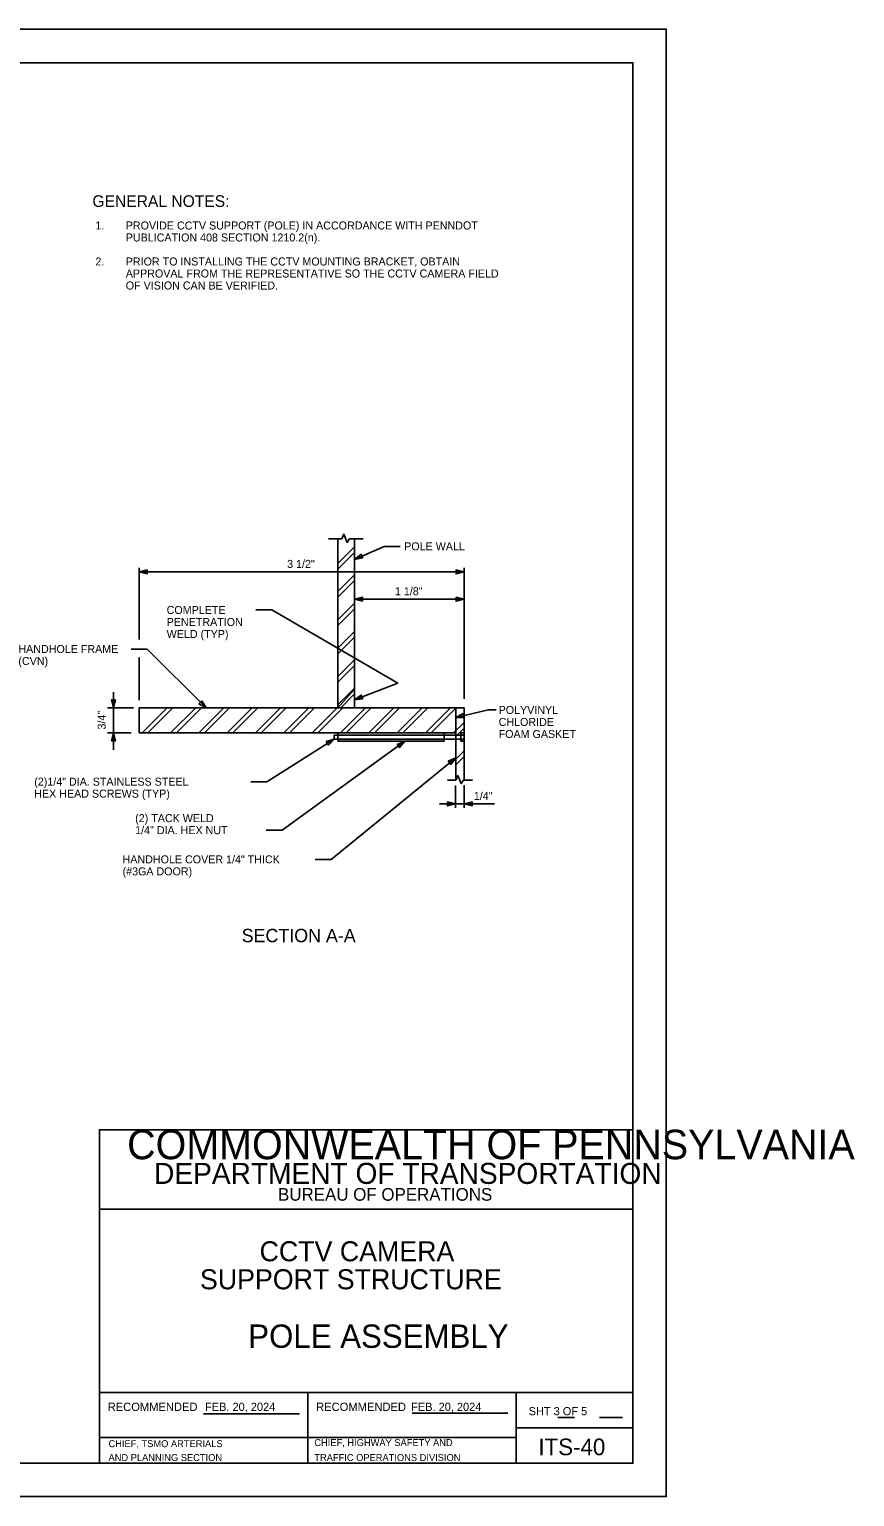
# Model space of a CAD drawing. Extents: x 1299104.7 to 1299141.5, y 239689.9 to 239711.9.
# Drawn here: x 1299129.17 to 1299141.55, y 239689.89 to 239711.89 of the extents above; entities that cross this region are included whole.
import ezdxf

# ---------------------------------------------------------------- set-up
doc = ezdxf.new("R2010")
doc.units = 0
for name, color, linetype in [('1', 7, 'Continuous'), ('2', 7, 'Continuous'), ('DIM TXT', 7, 'Continuous'), ('GS_plotshape_p', 7, 'Continuous'), ('Level 1', 7, 'Continuous'), ('Level 3', 7, 'Continuous'), ('Level 8', 7, 'Continuous'), ('PTEXT', 7, 'Continuous')]:
    doc.layers.add(name, color=color, linetype=linetype)

msp = doc.modelspace()

# ---------------------------------------------------------------- linework, layer by layer
at = {"layer": '1'}
for p, q in [((1299131.785, 239691.129), (1299133.222, 239691.129)), ((1299134.91, 239691.138), (1299136.347, 239691.138)), ((1299130.222, 239690.774), (1299133.347, 239690.774))]:
    msp.add_line(p, q, dxfattribs=at)
at = {"layer": 'DIM TXT'}
for p, q in [((1299138.722, 239711.886), (1299138.722, 239711.886)), ((1299133.742, 239701.302), (1299135.69, 239701.302)), ((1299133.742, 239701.245), (1299135.69, 239701.245)), ((1299135.565, 239701.302), (1299135.565, 239701.245)), ((1299135.643, 239701.211), (1299135.643, 239701.336)), ((1299135.643, 239701.336), (1299135.69, 239701.336)), ((1299135.643, 239701.211), (1299135.69, 239701.211)), ((1299138.722, 239689.886), (1299138.722, 239689.886))]:
    msp.add_line(p, q, dxfattribs=at)
at = {"layer": 'GS_plotshape_p'}
msp.add_lwpolyline([(1299104.722, 239711.886), (1299138.722, 239711.886), (1299138.722, 239689.886), (1299104.722, 239689.886)], close=True, dxfattribs=at)
at = {"layer": 'Level 1'}
for p, q in [((1299130.222, 239691.448), (1299138.222, 239691.448)), ((1299133.347, 239690.386), (1299133.347, 239691.448)), ((1299136.472, 239690.386), (1299136.472, 239691.448)), ((1299136.472, 239690.917), (1299138.222, 239690.917)), ((1299137.097, 239691.073), (1299137.347, 239691.073)), ((1299137.722, 239691.073), (1299138.066, 239691.073)), ((1299133.347, 239690.774), (1299136.472, 239690.774))]:
    msp.add_line(p, q, dxfattribs=at)
for points in [[(1299138.222, 239690.386), (1299106.222, 239690.386), (1299106.222, 239711.386), (1299138.222, 239711.386)], [(1299130.222, 239690.386), (1299138.222, 239690.386), (1299138.222, 239695.386), (1299130.222, 239695.386)], [(1299130.222, 239695.386), (1299138.222, 239695.386), (1299138.222, 239694.198), (1299130.222, 239694.198)]]:
    msp.add_lwpolyline(points, close=True, dxfattribs=at)
at = {"layer": 'Level 3'}
for p, q in [((1299133.798, 239704.246), (1299133.798, 239701.711)), ((1299134.048, 239704.246), (1299134.048, 239701.711)), ((1299135.69, 239701.711), (1299130.817, 239701.711)), ((1299130.817, 239701.336), (1299130.817, 239701.711)), ((1299135.565, 239701.336), (1299135.565, 239701.711)), ((1299135.69, 239700.628), (1299135.69, 239701.711)), ((1299130.817, 239701.336), (1299135.565, 239701.336)), ((1299133.742, 239701.302), (1299133.742, 239701.245)), ((1299133.797, 239701.336), (1299133.797, 239701.211)), ((1299134.256, 239701.336), (1299133.798, 239701.336)), ((1299135.391, 239701.336), (1299135.391, 239701.211)), ((1299135.565, 239700.628), (1299135.565, 239701.336)), ((1299133.797, 239701.211), (1299135.391, 239701.211))]:
    msp.add_line(p, q, dxfattribs=at)
for points in [[(1299134.048, 239701.994), (1299133.798, 239701.711), (1299134.048, 239701.711)], [(1299133.742, 239701.302), (1299133.742, 239701.245), (1299135.643, 239701.245), (1299135.643, 239701.211), (1299135.69, 239701.211), (1299135.69, 239701.336), (1299135.643, 239701.336), (1299135.643, 239701.302)]]:
    msp.add_lwpolyline(points, close=True, dxfattribs=at)
at = {"layer": 'Level 8'}
for p, q in [((1299133.659, 239704.246), (1299133.856, 239704.246)), ((1299133.798, 239703.879), (1299134.048, 239704.129)), ((1299133.974, 239704.246), (1299134.179, 239704.246)), ((1299134.048, 239703.939), (1299134.492, 239704.134)), ((1299134.732, 239704.134), (1299134.492, 239704.134)), ((1299133.798, 239703.794), (1299134.048, 239704.044)), ((1299133.798, 239703.879), (1299133.798, 239703.879)), ((1299130.817, 239702.735), (1299130.817, 239703.811)), ((1299130.817, 239703.751), (1299135.69, 239703.751)), ((1299133.798, 239703.455), (1299134.048, 239703.705)), ((1299135.69, 239701.847), (1299135.69, 239703.811)), ((1299133.798, 239703.37), (1299134.048, 239703.62)), ((1299135.69, 239703.56), (1299135.69, 239703.281)), ((1299133.798, 239703.03), (1299134.048, 239703.28)), ((1299134.048, 239703.066), (1299134.048, 239703.401)), ((1299134.048, 239703.341), (1299135.69, 239703.341)), ((1299132.566, 239703.18), (1299132.806, 239703.18)), ((1299133.798, 239702.946), (1299134.048, 239703.196)), ((1299133.798, 239702.606), (1299134.048, 239702.856)), ((1299133.798, 239702.521), (1299134.048, 239702.771)), ((1299130.701, 239702.595), (1299130.941, 239702.595)), ((1299131.821, 239701.711), (1299130.941, 239702.595)), ((1299130.817, 239701.83), (1299130.817, 239702.466)), ((1299133.798, 239702.182), (1299134.048, 239702.432)), ((1299133.798, 239702.097), (1299134.048, 239702.347)), ((1299130.432, 239701.949), (1299130.432, 239701.083)), ((1299133.798, 239701.758), (1299134.048, 239702.008)), ((1299133.84, 239701.715), (1299134.048, 239701.923)), ((1299130.734, 239701.712), (1299130.342, 239701.712)), ((1299130.866, 239701.336), (1299131.241, 239701.711)), ((1299130.951, 239701.336), (1299131.326, 239701.711)), ((1299131.291, 239701.336), (1299131.666, 239701.711)), ((1299131.376, 239701.336), (1299131.751, 239701.711)), ((1299131.715, 239701.336), (1299132.09, 239701.711)), ((1299131.8, 239701.336), (1299132.175, 239701.711)), ((1299132.139, 239701.336), (1299132.514, 239701.711)), ((1299132.224, 239701.336), (1299132.599, 239701.711)), ((1299132.563, 239701.336), (1299132.938, 239701.711)), ((1299132.648, 239701.336), (1299133.023, 239701.711)), ((1299132.988, 239701.336), (1299133.363, 239701.711)), ((1299133.073, 239701.336), (1299133.448, 239701.711)), ((1299133.412, 239701.336), (1299133.787, 239701.711)), ((1299133.497, 239701.336), (1299133.872, 239701.711)), ((1299133.836, 239701.336), (1299134.211, 239701.711)), ((1299133.921, 239701.336), (1299134.296, 239701.711)), ((1299134.261, 239701.336), (1299134.636, 239701.711)), ((1299134.345, 239701.336), (1299134.72, 239701.711)), ((1299134.685, 239701.336), (1299135.06, 239701.711)), ((1299134.77, 239701.336), (1299135.145, 239701.711)), ((1299135.109, 239701.336), (1299135.484, 239701.711)), ((1299135.194, 239701.336), (1299135.569, 239701.711)), ((1299135.565, 239701.57), (1299136.057, 239701.681)), ((1299136.169, 239701.681), (1299136.057, 239701.681)), ((1299135.533, 239701.336), (1299135.69, 239701.493)), ((1299130.698, 239701.336), (1299130.342, 239701.336)), ((1299133.742, 239701.245), (1299132.734, 239700.605)), ((1299135.565, 239701.283), (1299135.69, 239701.408)), ((1299134.8, 239701.211), (1299132.963, 239699.879)), ((1299135.565, 239700.944), (1299135.69, 239701.069)), ((1299135.565, 239700.964), (1299133.698, 239699.44)), ((1299135.565, 239700.859), (1299135.69, 239700.984)), ((1299132.494, 239700.605), (1299132.734, 239700.605)), ((1299135.442, 239700.628), (1299135.565, 239700.628)), ((1299135.674, 239700.628), (1299135.69, 239700.644)), ((1299135.683, 239700.628), (1299135.816, 239700.628)), ((1299135.562, 239700.549), (1299135.562, 239700.212)), ((1299135.691, 239700.553), (1299135.691, 239700.212)), ((1299135.322, 239700.272), (1299135.562, 239700.272)), ((1299135.562, 239700.272), (1299135.691, 239700.272)), ((1299136.148, 239700.272), (1299135.691, 239700.272)), ((1299132.723, 239699.879), (1299132.963, 239699.879)), ((1299133.458, 239699.44), (1299133.698, 239699.44))]:
    msp.add_line(p, q, dxfattribs=at)
for points in [[(1299133.856, 239704.246), (1299133.885, 239704.316), (1299133.938, 239704.194), (1299133.974, 239704.246)], [(1299134.048, 239701.833), (1299134.696, 239702.084), (1299132.806, 239703.18)], [(1299135.565, 239700.628), (1299135.594, 239700.698), (1299135.647, 239700.576), (1299135.683, 239700.628)]]:
    msp.add_lwpolyline(points, dxfattribs=at)
for points in [[(1299134.17, 239703.96), (1299134.048, 239703.939), (1299134.146, 239704.015)], [(1299130.937, 239703.721), (1299130.817, 239703.751), (1299130.937, 239703.781)], [(1299135.57, 239703.781), (1299135.69, 239703.751), (1299135.57, 239703.721)], [(1299134.168, 239703.311), (1299134.048, 239703.341), (1299134.168, 239703.371)], [(1299135.57, 239703.371), (1299135.69, 239703.341), (1299135.57, 239703.311)], [(1299134.171, 239701.848), (1299134.048, 239701.833), (1299134.149, 239701.904)], [(1299130.462, 239701.832), (1299130.432, 239701.712), (1299130.402, 239701.832)], [(1299131.758, 239701.817), (1299131.821, 239701.711), (1299131.715, 239701.775)], [(1299135.689, 239701.567), (1299135.565, 239701.57), (1299135.676, 239701.626)], [(1299130.402, 239701.216), (1299130.432, 239701.336), (1299130.462, 239701.216)], [(1299133.624, 239701.206), (1299133.742, 239701.245), (1299133.656, 239701.155)], [(1299134.686, 239701.164), (1299134.8, 239701.211), (1299134.721, 239701.116)], [(1299135.453, 239700.911), (1299135.565, 239700.964), (1299135.491, 239700.865)], [(1299135.442, 239700.302), (1299135.562, 239700.272), (1299135.442, 239700.242)], [(1299135.811, 239700.242), (1299135.691, 239700.272), (1299135.811, 239700.302)]]:
    msp.add_lwpolyline(points, close=True, dxfattribs=at)

# ---------------------------------------------------------------- texts
at = {"layer": '1'}
for s, height, p in [('COMMONWEALTH OF PENNSYLVANIA', 0.44223, (1299130.638, 239694.945)), ('DEPARTMENT OF TRANSPORTATION', 0.31514, (1299131.042, 239694.575)), ('BUREAU OF OPERATIONS', 0.18955, (1299132.901, 239694.323)), ('RECOMMENDED', 0.125, (1299130.347, 239691.17)), ('FEB. 20, 2024', 0.12303, (1299131.807, 239691.171)), ('RECOMMENDED', 0.125, (1299133.472, 239691.17)), ('FEB. 20, 2024', 0.12303, (1299134.897, 239691.171)), ('CHIEF, TSMO ARTERIALS ', 0.10417, (1299130.359, 239690.628)), ('CHIEF, HIGHWAY SAFETY AND ', 0.10417, (1299133.445, 239690.644)), ('AND PLANNING SECTION', 0.10417, (1299130.359, 239690.42)), ('TRAFFIC OPERATIONS DIVISION', 0.10417, (1299133.445, 239690.42))]:
    msp.add_text(s, height=height, dxfattribs=at).set_placement(p)
at = {"layer": '2'}
msp.add_text('SHT 3 OF 5', height=0.123, dxfattribs=at).set_placement((1299136.658, 239691.106))
at = {"layer": 'DIM TXT'}
for s, height, p in [('GENERAL NOTES:', 0.175, (1299130.118, 239709.223)), (' 1.', 0.12, (1299130.118, 239708.885)), ('PROVIDE CCTV SUPPORT (POLE) IN ACCORDANCE WITH PENNDOT ', 0.12, (1299130.618, 239708.885)), ('PUBLICATION 408 SECTION 1210.2(n).', 0.12, (1299130.618, 239708.705)), (' 2.', 0.12, (1299130.118, 239708.345)), ('APPROVAL FROM THE REPRESENTATIVE SO THE CCTV CAMERA FIELD ', 0.12, (1299130.618, 239708.165)), ('PRIOR TO INSTALLING THE CCTV MOUNTING BRACKET, OBTAIN ', 0.12, (1299130.618, 239708.345)), ('OF VISION CAN BE VERIFIED.', 0.12, (1299130.618, 239707.985)), ('POLE WALL', 0.12, (1299134.792, 239704.074)), ('3 1/2"', 0.12, (1299133.037, 239703.811)), ('1 1/8"', 0.12, (1299134.653, 239703.401)), ('COMPLETE', 0.12, (1299131.231, 239703.12)), ('PENETRATION', 0.12, (1299131.231, 239702.94)), ('WELD (TYP)', 0.12, (1299131.231, 239702.76)), ('HANDHOLE FRAME ', 0.12, (1299129.008, 239702.535)), ('(CVN)', 0.12, (1299129.008, 239702.355)), ('POLYVINYL', 0.12, (1299136.208, 239701.621)), ('CHLORIDE', 0.12, (1299136.208, 239701.441)), ('FOAM GASKET', 0.12, (1299136.208, 239701.261)), ('(2)1/4" DIA. STAINLESS STEEL', 0.12, (1299129.246, 239700.546)), ('HEX HEAD SCREWS (TYP)', 0.12, (1299129.246, 239700.366)), ('1/4"', 0.12, (1299135.836, 239700.332)), ('(2) TACK WELD', 0.12, (1299130.759, 239699.999)), ('1/4" DIA. HEX NUT', 0.12, (1299130.759, 239699.819)), ('HANDHOLE COVER 1/4" THICK', 0.12, (1299130.57, 239699.381)), ('(#3GA DOOR)', 0.12, (1299130.57, 239699.201)), ('SECTION A-A', 0.2, (1299132.356, 239698.199))]:
    msp.add_text(s, height=height, dxfattribs=at).set_placement(p)
msp.add_text('3/4"', height=0.12, rotation=90, dxfattribs=at).set_placement((1299130.316, 239701.388))
at = {"layer": 'PTEXT'}
for s, height, p in [('CCTV CAMERA', 0.3, (1299132.624, 239693.415)), ('SUPPORT STRUCTURE', 0.3, (1299131.73, 239692.995)), ('POLE ASSEMBLY', 0.35, (1299132.454, 239692.117)), ('ITS-40', 0.25, (1299136.804, 239690.507))]:
    msp.add_text(s, height=height, dxfattribs=at).set_placement(p)

doc.saveas('drawing.dxf')
